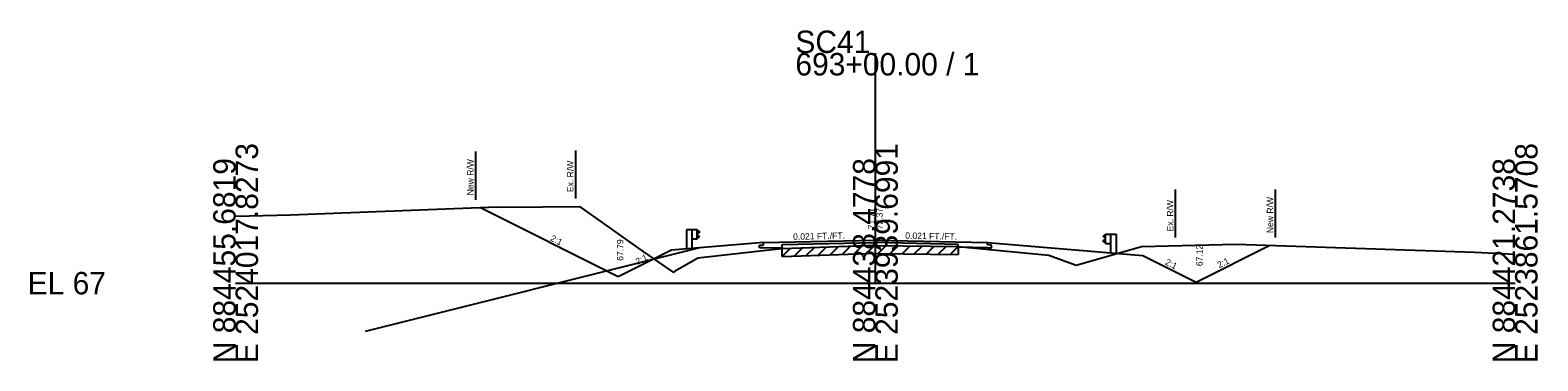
# Model space of a CAD drawing. Extents: x -26 to 183, y -10 to 24021.
# Drawn here: x -25.7 to 162.8, y 18490.3 to 18531.6 of the extents above; entities that cross this region are included whole.
import ezdxf

# ---------------------------------------------------------------- set-up
doc = ezdxf.new("R2010")
doc.units = 0
for name, color, linetype in [('RD_GPK_XS_Cell', 7, 'Continuous'), ('RD_XS_Base', 7, 'Continuous'), ('RD_XS_Buildup', 7, 'Continuous'), ('RD_XS_EarthShd', 7, 'Continuous'), ('RD_XS_ExGround', 7, 'Continuous'), ('RD_XS_ExPaveRet', 7, 'Continuous'), ('RD_XS_ExRW', 7, 'Continuous'), ('RD_XS_GR', 7, 'Continuous'), ('RD_XS_NewRW', 7, 'Continuous'), ('RD_XS_Pave', 7, 'Continuous'), ('RD_XS_TieSlope', 7, 'Continuous'), ('RD_XS_TX_Elev_EX', 7, 'Continuous'), ('RD_XS_TX_Elev_PR', 7, 'Continuous'), ('RD_XS_TX_Slope', 7, 'Continuous')]:
    doc.layers.add(name, color=color, linetype=linetype)

msp = doc.modelspace()

# ---------------------------------------------------------------- linework, layer by layer
at = {"layer": 'RD_GPK_XS_Cell'}
for p, q in [((80, 18500), (80, 18528.72)), ((0, 18500), (80, 18500)), ((80, 18500), (160, 18500))]:
    msp.add_line(p, q, dxfattribs=at)
at = {"layer": 'RD_XS_Base'}
for p, q in [((90.37, 18504.47), (90.37, 18504.56)), ((66, 18504.4), (68.36, 18504.45)), ((68.36, 18504.45), (68.36, 18504.32)), ((94, 18504.4), (90.37, 18504.47))]:
    msp.add_line(p, q, dxfattribs=at)
at = {"layer": 'RD_XS_Buildup'}
for p, q in [((68.36, 18504.81), (80, 18505.05)), ((68.36, 18504.32), (68.36, 18504.81)), ((90.37, 18504.83), (80, 18505.05)), ((90.37, 18504.56), (90.37, 18504.83))]:
    msp.add_line(p, q, dxfattribs=at)
at = {"layer": 'RD_XS_EarthShd'}
for p, q in [((66, 18505.08), (58, 18504.41)), ((94, 18505.08), (102, 18504.41)), ((58, 18504.41), (54.5, 18504.12)), ((102, 18504.41), (113.45, 18503.46))]:
    msp.add_line(p, q, dxfattribs=at)
at = {"layer": 'RD_XS_ExGround'}
for p, q in [((0, 18508.37), (6.86, 18508.53)), ((6.86, 18508.53), (31.61, 18509.47)), ((31.61, 18509.47), (38.41, 18509.53)), ((38.41, 18509.53), (43.01, 18509.57)), ((43.01, 18509.57), (51, 18503.9)), ((68.36, 18504.32), (78.96, 18504.7)), ((78.96, 18504.7), (79.35, 18504.72)), ((79.35, 18504.72), (80, 18504.71)), ((80, 18504.71), (90.37, 18504.56)), ((90.37, 18504.56), (101.67, 18503.5)), ((105.11, 18502.25), (113.26, 18504.58)), ((113.26, 18504.58), (125.12, 18504.86)), ((125.12, 18504.86), (154.98, 18503.87)), ((51, 18503.9), (54.74, 18501.33)), ((55.27, 18501.71), (57.81, 18503.16)), ((57.81, 18503.16), (67.11, 18504.18)), ((67.11, 18504.18), (68.36, 18504.32)), ((101.67, 18503.5), (105.11, 18502.25)), ((154.98, 18503.87), (160, 18503.6)), ((54.74, 18501.33), (55.27, 18501.71))]:
    msp.add_line(p, q, dxfattribs=at)
at = {"layer": 'RD_XS_ExPaveRet'}
for p, q in [((72.86, 18503.48), (73.9, 18504.52)), ((74.36, 18503.53), (75.4, 18504.57)), ((75.86, 18503.59), (76.9, 18504.63)), ((77.36, 18503.64), (78.4, 18504.68)), ((78.86, 18503.7), (79.87, 18504.71)), ((80.36, 18503.7), (81.34, 18504.69)), ((81.86, 18503.68), (82.84, 18504.67)), ((83.36, 18503.66), (84.34, 18504.65)), ((84.86, 18503.64), (85.84, 18504.62)), ((86.36, 18503.62), (87.34, 18504.6)), ((87.86, 18503.6), (88.84, 18504.58)), ((89.36, 18503.57), (90.34, 18504.56)), ((90.37, 18504.56), (90.37, 18503.56)), ((68.36, 18503.32), (69.4, 18504.35)), ((68.36, 18503.32), (68.36, 18504.32)), ((68.36, 18503.32), (78.96, 18503.7)), ((69.86, 18503.37), (70.9, 18504.41)), ((71.36, 18503.43), (72.4, 18504.46)), ((78.96, 18503.7), (79.35, 18503.72)), ((79.35, 18503.72), (80, 18503.71)), ((80, 18503.71), (90.37, 18503.56))]:
    msp.add_line(p, q, dxfattribs=at)
at = {"layer": 'RD_XS_ExRW'}
for p, q in [((42.5, 18516.57), (42.5, 18510.57)), ((117.5, 18511.68), (117.5, 18505.68))]:
    msp.add_line(p, q, dxfattribs=at)
at = {"layer": 'RD_XS_GR'}
for p, q in [((56.4, 18506.66), (56.4, 18504.28)), ((57.06, 18506.66), (56.4, 18506.66)), ((57.06, 18506.66), (57.06, 18504.33)), ((57.73, 18506.66), (57.06, 18506.66)), ((57.73, 18505.49), (57.73, 18506.66)), ((57.73, 18506.59), (58, 18506.39)), ((58, 18506.39), (58, 18506.34)), ((57.73, 18505.49), (57.06, 18505.49)), ((58, 18506.34), (57.73, 18506.14)), ((58, 18505.82), (57.73, 18506.02)), ((57.73, 18505.57), (58, 18505.77)), ((58, 18505.77), (58, 18505.82)), ((108.76, 18506.05), (108.49, 18505.85)), ((108.49, 18505.8), (108.49, 18505.85)), ((108.49, 18505.8), (108.76, 18505.6)), ((108.49, 18505.28), (108.76, 18505.48)), ((108.49, 18505.28), (108.49, 18505.23)), ((108.76, 18505.03), (108.49, 18505.23)), ((108.76, 18506.12), (109.42, 18506.12)), ((108.76, 18504.95), (108.76, 18506.12)), ((108.76, 18504.95), (109.43, 18504.95)), ((109.42, 18506.12), (109.42, 18503.79)), ((109.42, 18506.12), (110.09, 18506.12)), ((110.09, 18506.12), (110.09, 18503.74))]:
    msp.add_line(p, q, dxfattribs=at)
at = {"layer": 'RD_XS_NewRW'}
for p, q in [((30, 18516.41), (30, 18510.41)), ((130, 18511.7), (130, 18505.7))]:
    msp.add_line(p, q, dxfattribs=at)
at = {"layer": 'RD_XS_Pave'}
for p, q in [((65.5, 18504.75), (66, 18504.76)), ((65.5, 18504.39), (65.5, 18504.75)), ((66, 18505.08), (80, 18505.37)), ((66, 18504.76), (66, 18505.08)), ((80, 18505.37), (94, 18505.08)), ((94, 18504.76), (94, 18505.08)), ((94.5, 18504.75), (94, 18504.76)), ((94.5, 18504.39), (94.5, 18504.75)), ((58, 18504.41), (16.21, 18493.96)), ((66, 18504.4), (65.5, 18504.39)), ((94, 18504.4), (94.5, 18504.39))]:
    msp.add_line(p, q, dxfattribs=at)
at = {"layer": 'RD_XS_TieSlope'}
for p, q in [((47.83, 18500.79), (30.54, 18509.43)), ((120.12, 18500.12), (129.31, 18504.72)), ((54.5, 18504.12), (47.83, 18500.79)), ((113.45, 18503.46), (120.12, 18500.12))]:
    msp.add_line(p, q, dxfattribs=at)

# ---------------------------------------------------------------- texts
at = {"layer": 'RD_GPK_XS_Cell'}
for s, p in [('SC41', (70, 18528.72)), ('693+00.00 / 1', (70, 18525.92)), ('EL 67', (-26, 18498.6))]:
    msp.add_text(s, height=2.8, dxfattribs=at).set_placement(p)
for s, p in [('E 2524017.8273', (2.8, 18490)), ('E 2523939.6991', (82.8, 18490)), ('E 2523861.5708', (162.8, 18490)), ('N 884455.6819', (0, 18490)), ('N 884438.4778', (80, 18490)), ('N 884421.2738', (160, 18490))]:
    msp.add_text(s, height=2.8, rotation=90, dxfattribs=at).set_placement(p)
at = {"layer": 'RD_XS_ExRW'}
for p in [(42.25, 18511.36), (117.25, 18506.46)]:
    msp.add_text('Ex. R/W ', height=0.8, rotation=90, dxfattribs=at).set_placement(p)
at = {"layer": 'RD_XS_NewRW'}
for p in [(29.75, 18510.96), (129.75, 18506.24)]:
    msp.add_text('New R/W ', height=0.8, rotation=90, dxfattribs=at).set_placement(p)
at = {"layer": 'RD_XS_TX_Elev_EX'}
msp.add_text('71.71', height=0.8, rotation=90, dxfattribs=at).set_placement((79.9, 18506.71))
at = {"layer": 'RD_XS_TX_Elev_PR'}
for s, p in [('72.37', (80.9, 18506.71)), ('67.79', (48.48, 18502.79)), ('67.12', (120.92, 18502.12))]:
    msp.add_text(s, height=0.8, rotation=90, dxfattribs=at).set_placement(p)
at = {"layer": 'RD_XS_TX_Slope'}
for s, rotation, p in [('2:1', 333.4349, (39.28, 18505.34)), ('0.021 FT./FT.', 1.1916, (69.72, 18505.4)), ('0.021 FT./FT.', 358.8084, (83.73, 18505.54)), ('2:1', 26.5651, (50.27, 18502.28)), ('2:1', 333.4349, (116.16, 18502.36)), ('2:1', 26.5651, (123.01, 18501.85))]:
    msp.add_text(s, height=0.8, rotation=rotation, dxfattribs=at).set_placement(p)

doc.saveas('drawing.dxf')
